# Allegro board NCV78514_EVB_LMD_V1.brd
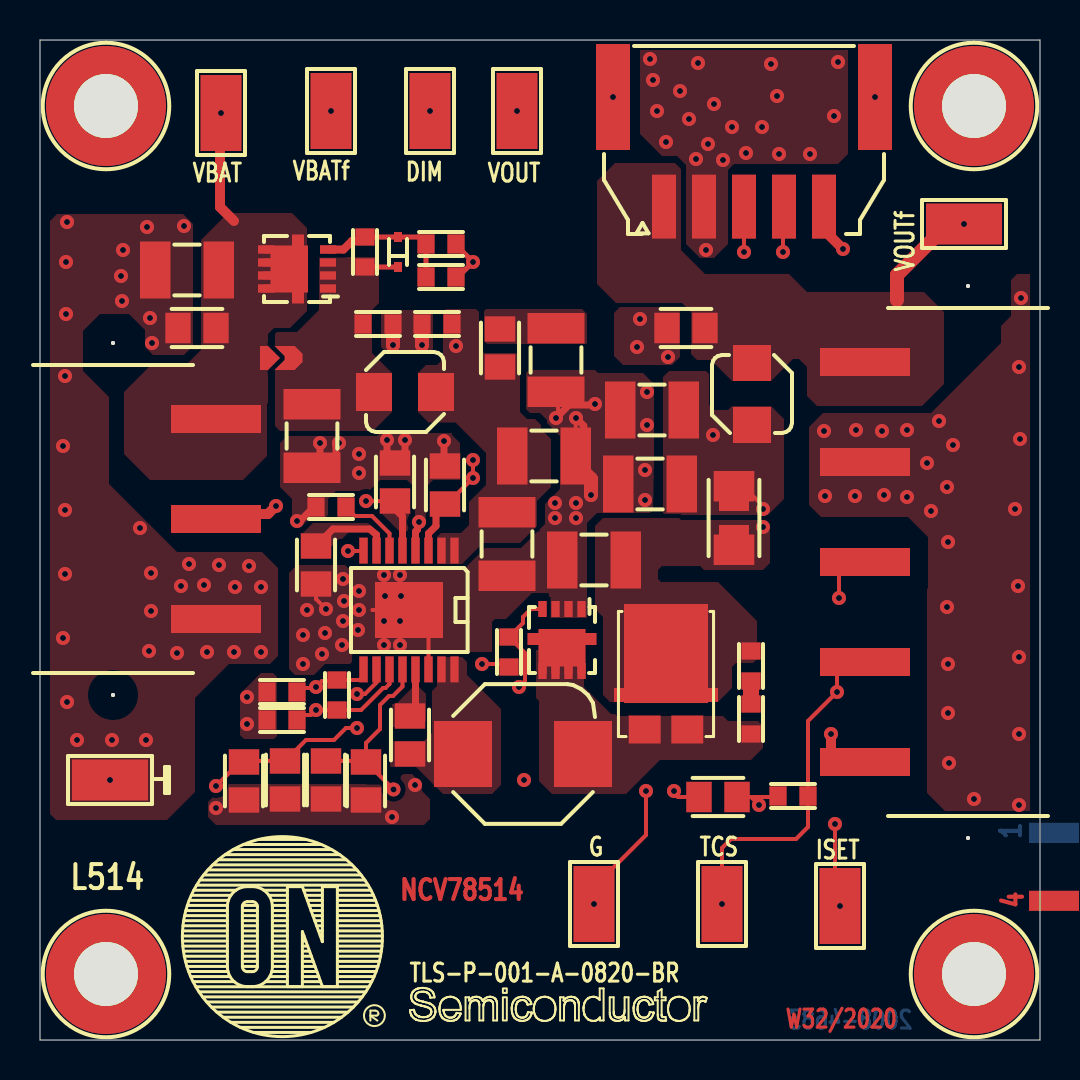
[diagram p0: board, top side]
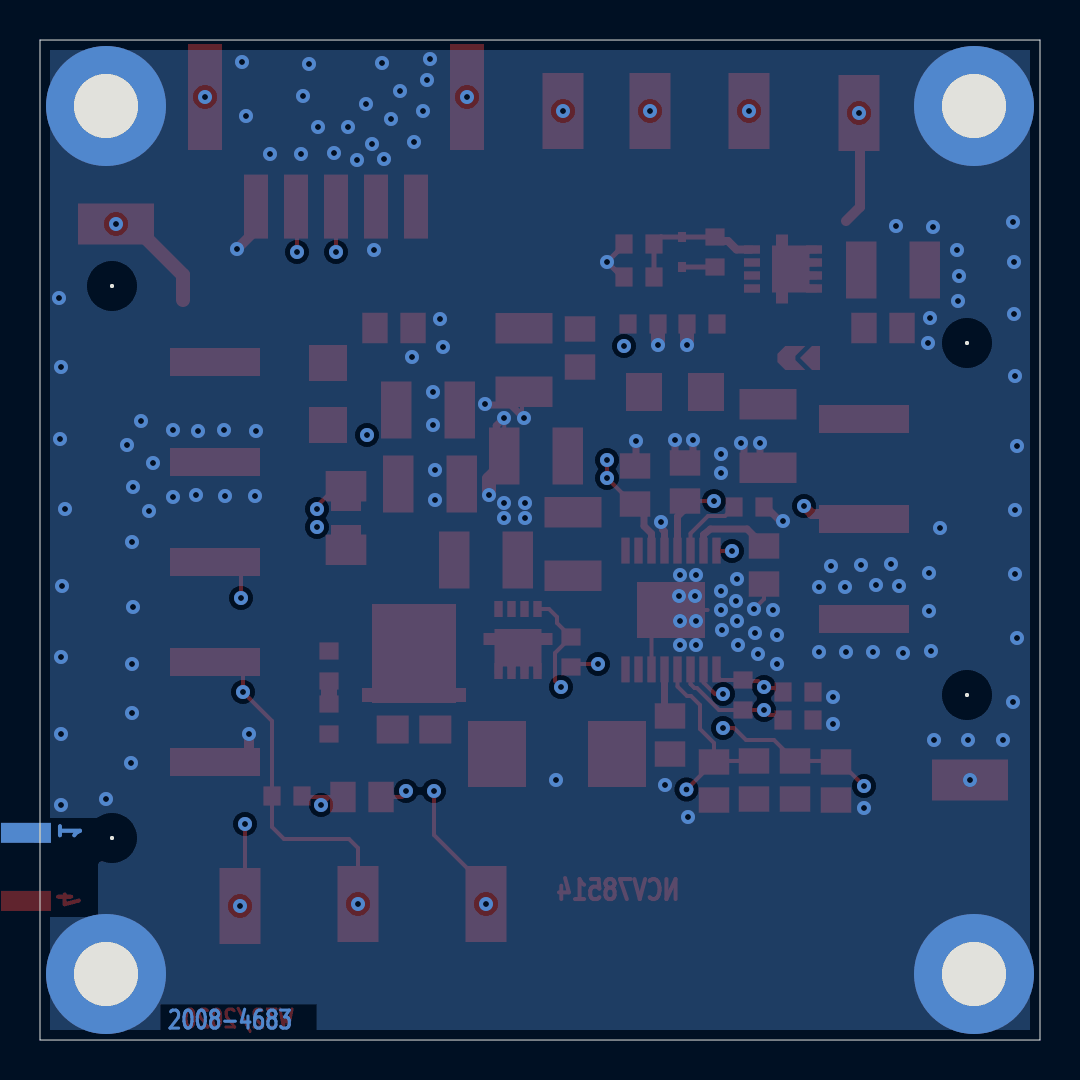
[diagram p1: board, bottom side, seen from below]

Outline 50 x 50 mm; copper layers: TOP, IN1, IN2, BOTTOM. Coordinates in mm from the lower left corner of the outline.
Outline path: 0,50 0,0 50,0 50,50 0,50

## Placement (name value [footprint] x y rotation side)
C1  100 nF  [805_603]  7.85 35.6 0 top
C2  10uF  [1210_1206]  7.35 38.5 0 top
C3  100 nF  [0603]  20.05 38.15 180 top
C4  10uF  [1210_1206]  13.6 30.2 90 top
C5  10uF  [1210_1206]  25.8 34 90 top
C6  10uF  [1210_1206]  25.2 29.2 180 top
C7  4.7uF  [1210_1206]  23.35 24.8 90 top
C8  1uF  [805_603]  20.25 27.75 270 top
C9  4.7uF  [805_603]  17.75 27.9 270 top
C10  4.7uF  [805_603]  13.8 23.75 90 top
C11  4.7uF  [1210_1206]  27.7 24 180 top
C12  100 nF  [0603]  12.1 16 0 top
C13  100 nF  [0603]  14.85 17.25 270 top
C14  100 nF  [0603]  12.1 17.4 0 top
C15  4.7uF  [1210_1206]  30.6 31.5 0 top
C16  4.7uF  [1210_1206]  30.5 27.8 0 top
C17  1uF  [805_603]  32.3 35.6 0 top
C18  1 uF  [805_603]  14.3 13 270 top
C19  1 uF  [805_603]  12.25 13 90 top
C20  100 nF  [805_603]  18.5 15.25 270 top
C21  1 nF  [0603]  35.55 18.7 90 top
C22  100 nF  [0603]  16.9 35.8 180 top
C23  100 nF  [0603]  19.85 35.8 0 top
D1  MM5Z15VT1G  [SOD-523]  17.9 39.4 90 top
D2  NRVTS8100PFST3G  [TO-277]  31.3 18.3 0 top
H1  fix  [FIX_M3_32_60]  3.3 46.7 0 top
H2  fix  [FIX_M3_32_60]  46.7 46.7 0 top
H3  fix  [FIX_M3_32_60]  46.7 3.3 0 top
H4  fix  [FIX_M3_32_60]  3.3 3.3 0 top
L1  10uH  [SELF_SPM7054]  24.15 14.3 180 top
L2  3.3 uH  [SELF_SPM4030]  18.25 32.4 180 top
L3  3.3 uH  [SELF_SPM4030]  35.6 32.3 270 top
NOREF  -  []  -294 -67.15 0 top
NOREF#2  -  []  0 0 90 top
NOREF#3  -  []  0 50 0 top
NOREF#4  -  []  0 50 0 top
NOREF#5  -  []  3.3 46.7 90 top
NOREF#6  -  []  -245.4 -64.6 0 top
NOREF#7  -  []  344.9 -47.2 180 bottom
R1  20k  [0603]  16.25 39.4 270 top
R2  10k  [0603]  20.05 39.8 180 top
R3  0R  [0603]  14.55 26.65 0 top
R4  0R  [0603]  37.65 12.2 180 top
R5  R100  [1206_0805]  34.7 26.1 270 top
R6  100R  [0603]  35.55 16.05 90 top
R7  0R  [0603]  23.45 19.4 90 top
R8  0R  [805_603]  23 34.6 270 top
R9  0R  [805_603]  10.2 12.95 270 top
R10  0R  [805_603]  16.3 12.95 90 top
R11  0R  [805_603]  33.9 12.15 0 top
S1  STRAP PCB  [STR_PCB]  11.5 34.1 0 top
TP1  Test Point  [PTEST_5019]  9.05 46.35 270 top
TP2  Test Point  [PTEST_5019]  14.55 46.45 270 top
TP3  Test Point  [PTEST_5019]  19.5 46.45 90 top
TP4  Test Point  [PTEST_5019]  3.5 13 0 top
TP5  Test Point  [PTEST_5019]  23.85 46.45 270 top
TP6  Test Point  [PTEST_5019]  46.2 40.8 0 top
TP7  Test Point  [PTEST_5019]  34.1 6.8 90 top
TP8  Test Point  [PTEST_5019]  40 6.7 270 top
TP9  Test Point  [PTEST_5019]  27.7 6.8 90 top
U1  Wurth Header 3  [WURTH_691709710303]  3.65 26.05 270 top
U2  MOLEX HEADER 5  [502352-0500]  35.2 45.1 0 top
U4  NVTFS5116PLTWG  [WDFN8_511AB]  12.85 38.55 180 top
U6  NCV78514  [TSSOP16_065-EP]  18.45 21.5 270 top
U7  NVTFS6H860NTAG  [WDFN8_511AB]  26.1 20 270 top
U8  WURTH HEADER 5  [WURTH_691709710305]  46.4 23.9 90 top

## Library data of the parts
C1-C23 = C
D1 = BZX84C33/SOT
D2 = V8PM10S
H1-H4 = HOLE
L1-L3 = Inductor_0
R1-R11 = R_0
S1 = STRAP PCB
TP1-TP9 = Test Point
U1 = MOLEX HEADER 3
U2 U8 = MOLEX HEADER 5
U4 = NVTFS5116PL
U6 = SCV78565
U7 = NVTFS5C680NL

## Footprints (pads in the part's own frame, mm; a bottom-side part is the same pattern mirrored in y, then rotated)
0603
  rect 0.86x0.96 smd: 1(-0.75,0) 2(0.75,0)
805_603
  rect 1.27x1.524 smd: 1(-0.953,0) 2(0.953,0)
1206_0805
  rect 1.524x2.032 smd: 1(-1.587,0) 2(1.587,0)
1210_1206
  rect 1.524x2.85 smd: 1(-1.587,0) 2(1.587,0)
502352-0500
  rect 1.2x3.2 smd: 1(-4,-3.43) 2(-2,-3.43) 3(0,-3.43) 4(2,-3.43) 5(4,-3.43)
  rect 1.7x5.3 smd: MM1(6.55,2.05) MM2(-6.55,2.05)
FIX_M3_32_60
  round 6 hole 3.2: 1(0,0)
PTEST_5019
  rect 3.8x2.05 smd: 1(0,0)
SELF_SPM4030
  rect 1.8x1.9 smd: 1(1.55,0) 2(-1.55,0)
SELF_SPM7054
  rect 2.9x3.3 smd: 1(3,0) 2(-3,0)
SOD-523
  rect 0.5x0.4 smd: 1(0.75,0) 3(-0.75,0)
STR_PCB
  custom 0.25x0.25 smd: 1(0,0)
  custom 0.3x0.3 smd: 2(0.93,0)
TO-277
  rect 1.6x1.4 smd: 1(1.065,-2.776) 2(-1.065,-2.776)
  rect 4.2x4.95 smd: 3(0,1.024)
TSSOP16_065-EP
  rect 1.3x0.42 smd: 1(-2.97,2.275) 2(-2.97,1.625) 3(-2.97,0.975) 4(-2.97,0.325) 5(-2.97,-0.325) 6(-2.97,-0.975) 7(-2.97,-1.625) 8(-2.97,-2.275) 9(2.97,-2.275) 10(2.97,-1.625) 11(2.97,-0.975) 12(2.97,-0.325) 13(2.97,0.325) 14(2.97,0.975) 15(2.97,1.625) 16(2.97,2.275)
  rect 2.8x3.4 smd: 17(0,0)
WDFN8_511AB
  rect 0.8x0.42 smd: 1(-1.55,0.975) 2(-1.55,0.325) 3(-1.55,-0.325) 4(-1.55,-0.975) 5(1.55,-0.975) 6(1.55,-0.325) 7(1.55,0.325) 8(1.55,0.975)
WURTH_691709710303
  round 0.2 hole 1.9 unplated: (-8.8,0) (8.8,0)
  rect 1.4x4.5 smd: 1(-5,5.15) 2(0,5.15) 3(5,5.15)
WURTH_691709710305
  round 0.2 hole 1.9 unplated: (-13.8,0) (13.8,0)
  rect 1.4x4.5 smd: 1(-10,5.15) 2(-5,5.15) 3(0,5.15) 4(5,5.15) 5(10,5.15)

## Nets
GND: C1.1 C2.1 C3.1 C4.1 C5.1 C6.1 C7.1 C8.1 C9.1 C10.1 C11.2 C12.1 C14.1 C15.1 C16.1 C17.1 C18.2 C19.1 C22.1 C23.1 H1.1 H2.1 H3.1 H4.1 R2.1 R3.1 R9.2 R10.1 TP4.1(TP) U1.3(GND) U2.2(LED-) U2.5(GND) U6.4(AGND) U6.14(PGND) U6.17(EP) U7.1(S#1) U7.2(S#2) U7.3(S#3) U8.1(LED+) U8.4(PTC)
PTC: C18.1 R4.2 R10.2 R11.2 U6.12(PTC)
PWM: C8.2 TP3.1(TP) U1.2(PWM) U6.3(PWM)
R_COD: C19.2 R9.1 TP8.1(TP) U2.3(R_COD) U6.10(ICOD) U8.3(R_COD)
TEST: R3.2 U6.6(TEST)
VLDO: C9.2 R11.1 U6.5(VLDO)
N16632032: C11.1 C12.2 C13.2 C21.2 D2.3(K) R5.2 U6.11(VLEDP)
N16632080: D2.1(A1) D2.2(A2) L1.2 R6.1 U7.5(D#5) U7.6(D#6) U7.7(D#7) U7.8(D#8)
N16632302: C6.2 C7.2 C23.2 L2.2 R8.2 TP2.1(TP) U6.1(VBAT#1) U6.2(VBAT#2)
N16632334: R7.2 TP9.1(TP) U7.4(G)
N16632604: C1.2 C2.2 S1.1 TP1.1(TP) U1.1(VBAT) U4.5(D#5) U4.6(D#6) U4.7(D#7) U4.8(D#8)
N16632624: C4.2 C22.2 D1.3(CATHODE) L2.1 R1.2 S1.2 U4.1(S#1) U4.2(S#2) U4.3(S#3)
N16632688: C20.2 L1.1 U6.15(SW#15) U6.16(SW#16)
N16632716: C13.1 C14.2 C15.2 C16.2 L3.1 R5.1 TP5.1(TP) U6.9(VLEDN)
N16632736: C17.2 L3.2 TP6.1(TP) U2.1(LED+) U8.5(GND)
N16632932: C20.1 U6.13(VBOOT)
N16632936: R4.1 TP7.1(TP) U2.4(PTC) U8.2(LED-)
N16632948: C3.2 D1.1(ANODE) R1.1 R2.2 U4.4(G)
N16633114: C10.2 U6.7(VDRV)
N16633242: R7.1 U6.8(BSTG)
N166320520: C21.1 R6.2
N166329161: C5.2 R8.1

Pads without a net: U2 MM1 MM2

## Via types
v1: diameter 0.7, hole 0.3, TOP to BOTTOM, 174 vias

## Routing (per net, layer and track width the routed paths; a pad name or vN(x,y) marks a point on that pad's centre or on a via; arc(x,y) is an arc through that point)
GND: length 44.5
  TOP w0.2: C6.1 26.79,31.09 v1(26.8,31.1) ; 25.9,31.2 25.9,32.01 ; v1(14.3,21.55) 13.8,22.05 C10.1 ; 25.91,24 25.82,23.91 ; U6.14 19.43,20.5 18.45,21.48 U6.17 16.62,21.5 ; 13.7,26.65 R3.1
  TOP w0.25: C3.1 20.9,38.15 v1(21.65,38.9) 20.8,39.75 R2.1
  TOP w0.35: v1(14,29.85) 14,29.01 C4.1 13.55,28.56 14.3,28.56 14.8,29.06 14.8,29.7 v1(14.95,29.85) ; v1(12.85,25.95) 13,25.95 13.7,26.65 ; U6.4 18.77,25.43 18.88,25.52 18.88,25.82 v1(18.95,25.9) ; v1(20.2,29.95) 20.2,28.75 C8.1 ; v1(26.8,31.1) 27.19,30.71 27.19,28.41 ; v1(27.75,31.8) 27.7,31.75 26.45,31.75 v1(25.8,31.1) ; v1(17.35,30) 17.35,29.25 C9.1 17.95,28.85 18.25,29.15 v1(18.25,30)
  TOP w0.5: v1(40.15,39.55) 39.2,40.5 U2.5 ; U8.1 40.05,13.9 39.55,14.4 v1(39.55,15.3)
  TOP w0.7: 27.19,28.41 27.55,28.05 v1(27.55,27.25) ; 17.65,35.85 C22.1 v1(17.65,34.75) ; v1(19.1,34.75) C23.1 19.1,35.85
  IN2 w0.7: v1(25.75,26.85) v1(25.75,26.1) v1(26.8,26.1) ; v1(25.75,26.85) v1(26.8,26.85) v1(26.8,26.1) ; v1(25.75,26.85) v1(26.8,26.1) ; v1(18,20.95) v1(17.2,20.95) ; v1(18,23.25) v1(17.2,23.25) ; v1(18.05,22.2) v1(17.25,22.2) ; v1(18,19.75) v1(17.2,19.75)
  vias: v1(1.15,29.7) v1(1.15,20.1) v1(1.25,33.2) v1(1.25,26.5) v1(1.25,23.3) v1(1.3,38.9) v1(1.3,36.3) v1(1.35,40.9) v1(1.35,16.9) v1(1.85,15) v1(3.5,13) v1(3.6,15) v1(4.05,38.2) v1(4.1,36.95) v1(4.15,39.5) v1(5,25.6) v1(5.35,40.65) v1(5.3,15) v1(5.5,36.1) v1(5.55,23.35) v1(5.55,21.45) v1(5.45,19.45) v1(5.6,34.85) v1(6.85,19.35) v1(7.05,22.7) v1(7.2,40.7) v1(7.45,23.8) v1(8.2,22.75) v1(8.35,19.4) v1(8.8,11.6) v1(8.95,23.75) v1(9.7,19.4) v1(9.75,22.65) v1(10.35,17.15) v1(10.35,15.8) v1(10.45,23.7) v1(11.05,22.65) v1(11.05,19.4) v1(13.15,20.25) v1(13.15,18.8) v1(13.35,21.5) v1(14.1,19.3) v1(14.25,20.35) v1(15.1,19.75) v1(15.15,23.05) v1(15.2,21.95) v1(15.15,20.95) v1(15.95,29.3) v1(15.95,28.35) v1(15.95,22.45) v1(15.95,21.5) v1(15.9,20.5) v1(17.6,11.15) v1(18.75,12.75) v1(24.2,13) v1(29.85,34.65) v1(30,36.05) v1(30.25,28.5) v1(30.25,27) v1(30.35,32.4) v1(30.35,30.75) v1(30.5,49.05) v1(30.65,48) v1(30.85,46.45) v1(31.3,44.9) v1(31.4,34.15) v1(32,47.45) v1(32.45,46.05) v1(32.8,44.05) v1(32.9,48.85) v1(33.3,39.5) v1(33.4,44.8) v1(33.7,46.8) v1(34.15,44) v1(34.6,45.65) v1(35.3,44.35) v1(36.1,45.65) v1(36.55,48.8) v1(36.85,47.2) v1(36.95,44.3) v1(38.5,44.3) v1(39.2,30.45) v1(39.25,27.2) v1(39.7,46.2) v1(39.9,48.9) v1(40.8,30.5) v1(40.75,27.2) v1(42.1,30.45) v1(42.2,27.25) v1(43.35,30.5) v1(43.35,27.15) v1(44.35,28.85) v1(44.55,26.45) v1(44.95,30.95) v1(45.35,27.65) v1(45.4,24.9) v1(45.35,21.65) v1(45.4,18.8) v1(45.4,16.35) v1(45.45,13.85) v1(45.65,29.75) v1(46.7,12.05) v1(48.75,26.55) v1(48.9,22.7) v1(49.05,37.1) v1(48.95,33.65) v1(49,30.05) v1(48.95,19.15) v1(48.95,15.3) v1(48.95,11.75)
Net_19:
  vias: v1(28.65,47.15)
Net_20:
  vias: v1(41.75,47.15)
PTC: length 31.2
  TOP w0.2: R4.2 36.85,12.15 35.55,12.15 ; R10.2 16.3,14.85 17,15.55 17,16.75 17.45,17.2 17.65,17.2 18.12,17.68 U6.12 ; R10.2 v1(17.68,12.53) ; R10.2 16.25,13.95 C18.1 ; 35.55,12.15 R11.2 ; 35.55,12.15 v1(35.95,11.75)
  IN2 w0.2: v1(35.95,11.75) 35.25,11.75 34.7,11.2 28.8,11.2 28.25,11.75 18.8,11.75 18.02,12.53 v1(17.68,12.53)
PWM: length 38.4
  TOP w0.2: v1(21.65,29) v1(21.65,28.1) 20.55,27 ; C8.2 20.2,26.85
  TOP w0.25: 20.55,27 20.45,27 C8.2
  TOP w0.35: 20.2,26.85 19.8,26.45 19.8,25.7 19.43,25.32 U6.3
  TOP w0.5: v1(11.8,26.7) 11.4,26.3 9.05,26.3 U1.2
  IN2 w0.25: v1(11.8,26.7) 12.75,27.65 16.35,27.65 16.8,28.1 v1(21.65,28.1) ; v1(21.65,29) 21.65,30.85 22.55,31.75 22.55,36.6 20.35,38.8 20.35,45.6 v1(19.5,46.45)
R_COD: length 89.5
  TOP w0.2: U6.10 16.82,17.88 16.25,17.3 v1(15.85,17.3) ; v1(35.2,39.4) U2.3 ; v1(39.95,22.1) 39.95,23.7 40.15,23.9 U8.3 ; v1(39.75,10.8) 39.75,6.95 v1(40,6.7) ; v1(8.8,12.7) 10,13.9 R9.1 10.25,13.95 C19.2 12.25,13.95 13.3,15 14.7,15 15.3,15.6 v1(15.85,15.6)
  IN2 w0.2: v1(8.8,12.7) 16,12.7 16.9,11.8 17.9,11.8 18.6,11.1 28,11.1 28.4,10.7 39.65,10.7 v1(39.75,10.8) 41.25,12.3 41.25,20.8 v1(39.95,22.1) 41.45,23.6 41.45,37.05 37.75,40.75 36.55,40.75 v1(35.2,39.4) ; v1(15.85,17.3) v1(15.85,15.6)
TEST: length 3.6
  TOP w0.2: 17.48,24.47 17.48,25.32 16.6,26.2 15.75,26.2 R3.2
VLDO: length 46.5
  TOP w0.2: R11.1 31.9,12.15 31.7,12.35 v1(31.7,12.45) ; C9.2 v1(16.3,26.95)
  TOP w0.35: C9.2 17.75,26.55 18.12,26.17 U6.5
  IN2 w0.2: v1(31.7,12.45) 31.7,13.75 37.35,19.4 37.35,23.85 37.75,24.25 37.75,27.15 36.75,28.15 32.9,28.15 30,25.25 24.45,25.25 23.7,26 20.5,26 19.9,26.6 16.65,26.6 v1(16.3,26.95)
N16632032: length 35.3
  TOP w0.2: 36.05,25.75 v1(36.15,25.65) ; 17.48,18.53 17.48,17.8 17.27,17.6 17.15,17.6 16.05,16.5 C13.2 v1(13.8,16.5) 13.55,16.25 13.1,16.25 C12.2 ; 31.1,19.75 31.1,19.32 32.07,18.35
  IN2 w0.2: v1(13.8,16.5) 13.8,16.7 14.05,16.95 14.45,16.95 15.7,18.2 17.55,18.2 18.5,17.25 22.4,17.25 25.95,20.8 29.05,20.8 34.15,25.9 35.9,25.9 v1(36.15,25.65)
N16632080: length 0.1
  TOP w0.2: 27.05,14.5 27,14.55
N16632302: length 14.3
  IN2 w0.25: v1(20.8,34.7) 14.55,40.95 v1(14.55,46.45)
N16632334: length 20.7
  TOP w0.2: v1(27.7,6.8) 27.7,7.65 30.3,10.25 v1(30.3,12.45) ; U7.4 24.55,21.55 24.15,21.15 24.15,20.85 R7.2 24.25,19.35 24.25,17.95 v1(23.95,17.65)
  IN2 w0.2: v1(30.3,12.45) 30.3,12.55 25.2,17.65 v1(23.95,17.65)
N16632604: length 7.4
  TOP w0.2: 9,47.2 9.05,47.15 v1(9.05,46.35)
  TOP w0.5: 9,47.2 9,41.65 9.7,40.95
N16632624: length 1.6
  TOP w0.25: D1.3 R1.2
N16632716: length 54.1
  TOP w0.2: R5.1 35.16,27.69 36.15,26.7 v1(36.15,26.55) ; C14.2 13.05,17.6 13.75,17.6 v1(13.8,17.65) 14.1,17.95 14.75,17.95 14.8,18 C13.1 15.97,18 16.18,18.2 U6.9
  IN2 w0.2: v1(13.8,17.65) 13.8,17.62 14.05,17.37 14.27,17.37 15.52,18.62 17.73,18.62 18.68,17.67 22.22,17.67 25.8,21.25 28.9,21.25 33.95,26.3 35.9,26.3 v1(36.15,26.55)
  IN2 w0.5: v1(23.85,46.45) 23.85,38.7 28.95,33.6 30.3,33.6 v1(33.65,30.25)
N16632736: length 5.7
  TOP w0.7: v1(46.2,40.8) 45.4,40.8 42.85,38.25 42.85,37
N16632932: length 2.6
  TOP w0.35: U6.13 18.77,16.53 18.45,16.2 18.3,16.2
N16632936: length 44.2
  TOP w0.2: v1(34.1,6.8) 34.1,9.6 34.55,10.05 37.8,10.05 38.4,10.65 R4.1 38.4,15.95 v1(39.85,17.4) 39.85,18.7 40.05,18.9 U8.2 ; U2.4 37.15,41.62 v1(37.15,39.4)
  IN2 w0.2: v1(39.85,17.4) 38.65,18.6 38.65,22.8 40,24.15 40,36.55 v1(37.15,39.4)
N16632948: length 7
  TOP w0.25: C3.2 R2.2 18.95,40.15 D1.1 R1.1
  TOP w0.4: U4.4 15.18,39.52 15.6,39.95 16.05,39.95 R1.1
N16633114: length 4.3
  TOP w0.35: C10.2 14.65,25.55 16.48,25.55 16.82,25.26 U6.7
N16633242: length 13.4
  TOP w0.2: U6.8 16.18,24.45 v1(15.4,24.45) ; R7.1 23.45,18.7 23.35,18.8 v1(22.1,18.8)
  IN2 w0.3: v1(22.1,18.8) 21.8,19.1 21.8,22.8 20.15,24.45 v1(15.4,24.45)
N166320520: length 1.1
  TOP w0.8: R6.2 C21.1

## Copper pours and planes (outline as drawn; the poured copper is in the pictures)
GND on TOP: 33,39.1 32.3,39.8 32.3,43.75 31.85,44.2 31.1,44.2 30,45.3 30,49.5 40.4,49.5 40.4,44.3 39.9,43.8 34.7,43.8 34.4,43.5 34.4,39.8 33.7,39.1
GND on TOP: 45.25,11.45 44.35,12.35 44.35,22.55 44.4,22.6 44.4,25.15 43.4,26.15 39.05,26.15 38.45,26.75 38.45,30.65 39.15,31.35 44.55,31.35 48.05,34.85 48.05,35.7 48.55,36.2 48.55,38 48.85,38.3 49.5,38.3 49.5,11.45
GND on TOP: 12.45,23.35 12.85,23.75 15.25,23.75 15.4,23.6 21.25,23.6 22.25,24.6 24.05,24.6 25.25,25.8 25.25,26.8 25.6,27.15 26.9,27.15 27.35,26.7 27.35,21.1 25.45,21.1 25.45,22.3 25.4,22.35 24.6,22.35 23.3,21.05 22.75,21.05 22.6,20.9 22.6,19.4 15.75,19.4 15.6,19.25 15.6,18.9 15.5,18.8 14.25,18.8 13.7,18.25 12.75,18.25 12.45,18.55
GND on TOP: 32,34.15 32,36.55 31.85,36.7 29.05,36.7 28.7,36.35 28.7,34.2 29.15,33.75 31.6,33.75
GND on TOP: 11.85,15.2 11.85,18.15 11.65,18.35 11.05,18.35 10,17.3 10,15.25 10.2,15.05 11.7,15.05
GND on TOP: 0.8,11 0.5,11.3 0.5,40.95 0.85,41.3 7.15,41.3 7.65,40.8 7.65,34.7 7.2,34.25 5.65,34.25 5.25,34.65 5.25,35.5 4.45,36.3 3,36.3 2.15,35.45 2.15,33.45 3.45,32.15 3.45,27.8 6.85,24.4 11.1,24.4 11.9,23.6 11.9,19.2 11.5,18.8 9.45,18.8 7.75,17.1 7.75,12.4 6.35,11
GND on TOP: 25.35,31 25.35,30.85 26,30.2 26,27.55 25.45,27 25.45,25.65 25.5,25.6 27.1,25.6 27.85,26.35 30.5,26.35 30.65,26.5 30.7,28.91 30.7,32.8 30.15,33.35 27.9,33.35 27.75,33.5 24.45,33.5 24.3,33.35 24.3,31.55 24.5,31.35 25,31.35
GND on TOP: 16.3,12.8 9.3,12.8 8.4,11.9 8.4,11.15 8.8,10.75 19.2,10.75 19.5,11.05 19.5,12.05 19.1,12.45 19.1,12.8 18.6,13.3 17.7,13.3 17.18,12.78 16.32,12.78
GND on TOP: 20.6,30.35 17,30.35 16.85,30.2 12.35,30.2 12,29.85 12,27.65 12.6,27.05 12.6,25.8 12.75,25.65 13.05,25.65 13.55,26.15 14.3,26.15 14.4,26.25 14.4,27.05 14.8,27.45 16.45,27.45 17,28 18.35,28 18.75,27.6 18.75,25.75 18.8,25.7 19.15,25.7 19.3,25.85 19.3,27.65 19.65,28 21,28 21,29.85 20.6,30.25
GND on TOP: 19.5,36.5 17.2,36.5 17.05,36.35 17.05,34.65 17.4,34.3 19.4,34.3 19.65,34.55 19.65,36.35
GND on BOTTOM: 0.5,0.5 0.5,49.5 49.5,49.5 49.5,11.1 47.1,11.1 47.1,6.15 49.5,6.15 49.5,0.5
GND on IN1: 0.5,0.5 0.5,49.5 49.5,49.5 49.5,11.05 47.05,11.05 47.05,6.15 49.5,6.15 49.5,0.5
GND on IN2: 0.5,0.5 0.5,49.5 49.5,49.5 49.5,0.5
Net_26 on BOTTOM (solid shape): 51.95,9.86 49.45,9.86 49.45,10.86 51.95,10.86
Net_27 on IN2 (solid shape): 51.95,8.76 49.45,8.76 49.45,9.76 51.95,9.76
Net_28 on IN1 (solid shape): 51.95,7.61 49.45,7.61 49.45,8.61 51.95,8.61
Net_29 on TOP (solid shape): 51.95,6.46 49.45,6.46 49.45,7.46 51.95,7.46
VLDO on TOP: 18.45,25.55 18.3,25.4 18,25.4 17.05,26.35 17.05,27.25 17.2,27.4 18.45,27.4
N16632032 on TOP (solid shape): 35.45,24.1 33.95,24.1 33.95,25.75 35.45,25.75
N16632032 on TOP (solid shape): 33.3,19 33.3,17.6 33.9,17.6 33.9,16.9 28.7,16.9 28.7,17.6 29.2,17.6 29.2,19 30.1,19.9 32.4,19.9
N16632032 on TOP: 28.5,16.9 33.9,16.9 34.6,17.6 34.6,18.65 34.8,18.85 35.65,18.85 35.85,19.05 35.85,20.95 33.9,22.9 31.05,22.9 30.9,23.05 30.9,23.5 31.1,23.7 33,23.7 33.2,23.5 36.15,23.5 36.5,23.85 36.5,25.45 35.95,26 32.05,26 31.95,26.1 28.15,26.1 27.75,25.7 27.75,21.55 28.15,21.15 28.15,17.25
N16632080 on TOP (solid shape): 27.27,20.35 27.82,20.35 27.82,19.75 27.27,19.75 27.27,18.3 26.88,18.3 26.88,18.68 26.62,18.68 26.62,18.3 26.23,18.3 26.23,18.68 25.98,18.68 25.98,18.3 25.57,18.3 25.57,18.68 25.32,18.68 25.32,18.3 24.93,18.3 24.93,19.75 24.38,19.75 24.38,20.35 24.93,20.35 24.93,20.55 27.27,20.55
N16632080 on TOP: 28.85,16.2 34.15,16.2 34.4,15.95 35.9,15.95 36.15,15.7 36.15,14.6 35.55,14 31,14 29.3,12.3 25.6,12.3 24.95,12.95 24.95,16.95 24.8,17.1 24.8,19.5 26.9,19.5 27.2,19.2 27.2,17.65 28.55,16.3 28.75,16.3
N16632302 on TOP: 19.85,25.15 19.85,23.8 21.1,23.8 22.15,24.85 24,24.85 24.85,25.7 24.85,26.95 25.55,27.65 25.55,30.05 25.05,30.55 25.05,30.75 24.75,31.05 24.35,31.05 24,31.4 24,34.15 23.8,34.35 22.2,34.35 21.95,34.6 21.95,36.4 21.8,36.55 20.3,36.55 20.15,36.4 20.15,34.05 19.85,33.75 19.3,33.75 18.9,33.35 18.9,31.4 19.43,30.88 20.77,30.88 22.3,29.35 22.3,27.75 21.45,26.9 21.45,25.75 21.05,25.35 20.05,25.35
N16632604 on TOP (solid shape): 13.2,39.73 13.4,39.73 13.4,37.38 13.2,37.38 13.2,36.83 12.6,36.83 12.6,37.38 11.15,37.38 11.15,37.77 11.53,37.77 11.53,38.02 11.15,38.02 11.15,38.42 11.53,38.42 11.53,38.67 11.15,38.67 11.15,39.08 11.53,39.08 11.53,39.33 11.15,39.33 11.15,39.73 12.6,39.73 12.6,40.27 13.2,40.27
N16632604 on TOP: 11.35,31.8 11.35,29.2 10.15,28 5.5,28 4.2,29.3 4.2,32.4 5.6,33.8 7.35,33.8 8.05,34.5 8.05,40 9.4,41.35 12.6,41.35 13.35,40.6 13.35,36.45 12.5,35.6 11.7,35.6 11.4,35.3 11.4,34.6 11.9,34.1 11.9,34.05 11.4,33.55 11.4,31.85
N16632624 on TOP: 12.35,34.1 11.75,33.5 11.75,30.7 12,30.45 16.65,30.45 17.6,31.4 17.6,33.35 16.6,34.35 16.6,36.5 16.95,36.85 16.95,38.95 16.75,39.15 13.95,39.15 13.95,36.5 12.85,35.4 11.85,35.4 11.75,35.3 11.75,34.7
N16632688 on TOP: 21.1,19.15 19.95,19.15 19.85,19.05 19.85,17.7 19.6,17.45 19.6,15.35 19.2,14.95 17.6,14.95 17.5,14.85 17.5,13.7 17.55,13.65 18.8,13.65 20.15,12.3 22.6,12.3 23.05,12.75 23.05,16.55 21.35,18.25 21.35,18.9
N16632716 on TOP (solid shape): 35.45,26.45 33.95,26.45 33.95,28.05 35.45,28.05
N16632716 on TOP: 31.25,26.25 36.4,26.25 37.2,27.05 37.2,31.05 36.55,31.7 34.6,31.7 34.4,31.5 33.7,31.5 33.45,31.75 33.45,33.3 33.3,33.45 31.45,33.45 31.15,33.15 31.15,26.35
N16632736 on TOP: 34.6,32.95 36.55,32.95 37.65,34.05 37.95,34.05 38.35,33.65 38.35,32.2 38.85,31.7 44.1,31.7 45.2,32.8 45.2,36.4 44.2,37.4 38.35,37.4 37.45,38.3 33.25,38.3 32.05,39.5 32.05,43.55 31.75,43.85 28.75,43.85 27.85,42.95 27.85,37.8 28.8,36.85 32.1,36.85 32.55,36.4 32.55,34.3 32.85,34 33.55,34
N16632932 on TOP: 17.6,16.8 17.6,15.7 17.65,15.65 19,15.65 19.3,15.95 19.3,17.3 18.9,17.7 18.9,18.85 18.8,18.95 18.7,18.95 18.6,18.85 18.6,17.6 17.8,16.8
N16633114 on TOP: 14.95,25.05 15.1,25.05 15.45,25.4 16.4,25.4 16.6,25.6 16.6,25.65 16.4,25.85 13.65,25.85 13.1,25.3 13.1,24.45 13.3,24.25 14.15,24.25
N166329161 on TOP: 22.2,36.45 22.2,34.95 22.35,34.8 27.3,34.8 27.35,34.85 27.35,36.3 27.1,36.55 22.3,36.55

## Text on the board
BOTTOM: 2008-4683 | 1 | face1bot
Ref Des/Silkscreen Bottom: silk bot
User.Comments: ve bot | ve top
TOP: W32/2020 | NCV78514 | 4 | face4top
Ref Des/Silkscreen Top: VBAT | VBATf | DIM | TLS-P-001-A-0820-BR | VOUT | G | TCS | ISET | VOUTf | L514 | silk top
IN1: 3 | face3
IN2: 2 | face2
BODY_CENTER: 2 | 3 | 7 | 4 | 8 | 5 | 9 | 6 | 1
ASSEMBLY_TOP: 1.0 | TP4 | TP6 | TP1 | TP2 | TP3 | TP5 | TP9 | TP7 | TP8 | H4 | H1 | H2 | H3 | C12 | C14 | S1 | R3 | C22 | L2 | C23 | R2 | C3 | C6 | C15 | C16 | C17 | R11 | R4 | D1 | C19 | C10 | C18 | C13 | R1 | R10 | C9 | C20 | C8 | R7 | C5 | R6 | C21 | L3 | R9 | C11 | R8 | U4 | U7 | D2 | U2 | C2 | C1 | U6 | L1 | C4 | C7 | R5 | U1 | U8 | RoHs compliant | SCALE 4:1
User.5: week xx/2009
User.6: OVER 5um(0.2mils) NICKEL | 0.05um(0.002mils)GOLD/ | VIA | Soldermask | 35u+metal | 35u | THICKNESS | MATERIAL | STACKUP | FINISH | SILKSCREEN | MINIMAL GAP | MINIMAL SLIVER | BOARD THICKNESS | SOLDER MASK | COPPER THICKNESS | MARKED ON TOP SILKSCREEN | ALL BOARD ELECTRICALLY TESTED | MANUFACTURE 'S LOGO & DATECODE | COMPLIANT RoHS DIRECTIVE 2011/65/EU | MC4  /4LAYERS | Black TOP | FR4 HTG180 (low CTE) | CHEMICAL  NiAu | 200um /7.8mils | White TOP & BOT | 35um(1oz) | at start | 1.0mm /39mils | 1.0 | plugged and capped | All 0.3mm Via must be | SPEC:
User.8: S32/2020 DYPE TECH | NCV78514 LMD | rev 1
User.11: FIGURE | SIZE | 0.3 | 3.2 | 1.9 | DRILL CHART: TOP to BOTTOM | ALL UNITS ARE IN MILLIMETERS | PLATED | NON-PLATED | QTY | 174 | 4
